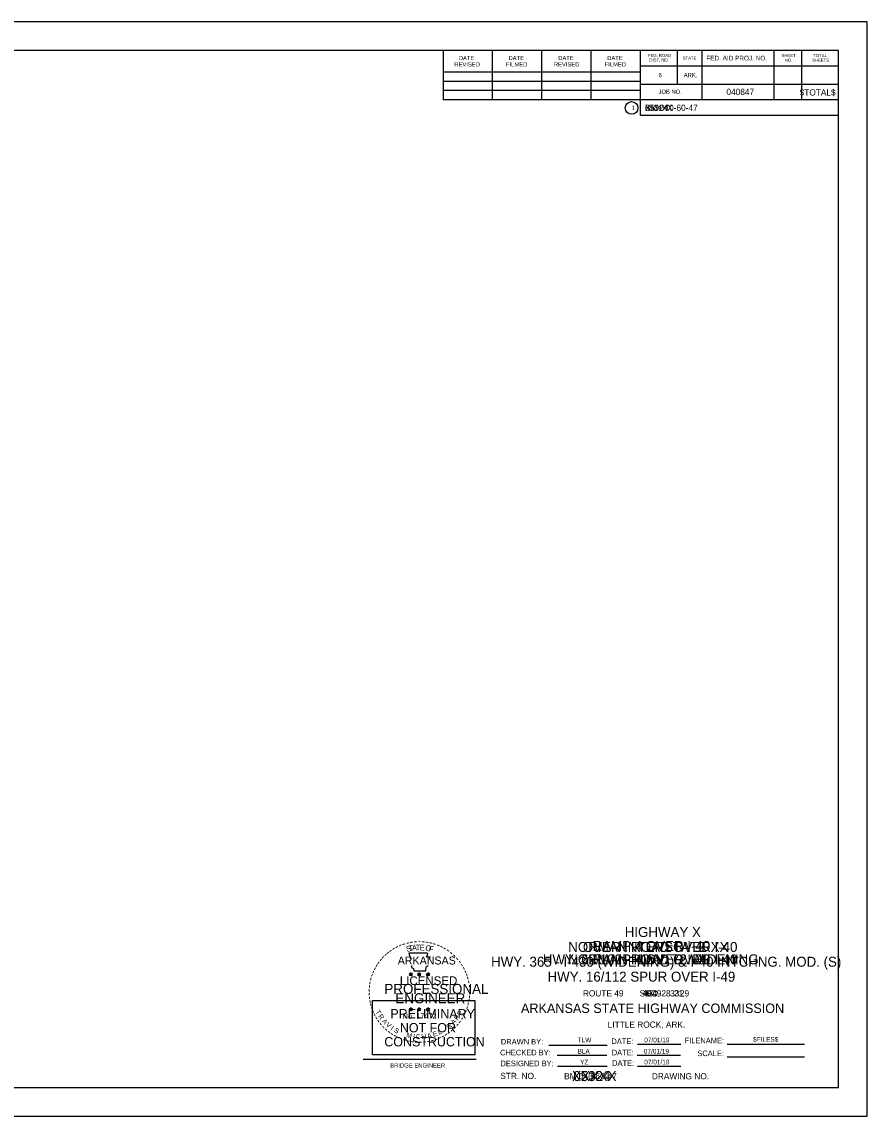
# Model space of a CAD drawing. Extents: x 0 to 2.83, y -2.82 to 1.83.
import ezdxf

# ---------------------------------------------------------------- set-up
doc = ezdxf.new("R2010")
doc.units = 0
for name, color, linetype in [('1', 7, 'Continuous'), ('B-Seal', 7, 'Continuous'), ('B-Tbl-BM0406045', 7, 'Continuous'), ('B-Tbl-BM0406047', 7, 'Continuous'), ('B-Tbl-Bridge A - Details', 7, 'Continuous'), ('B-Tbl-Bridge A - Layout', 7, 'Continuous'), ('B-Tbl-Bridge B - Details', 7, 'Continuous'), ('B-Tbl-Bridge B - Layout', 7, 'Continuous'), ('B-Tbl-Bridge E', 7, 'Continuous'), ('B-Tbl-Bridge F', 7, 'Continuous'), ('B-Tbl-Prelim', 7, 'Continuous'), ('B-Tbl-Title Block', 7, 'Continuous'), ('B-Tbl-Title Block Major Text', 7, 'Continuous'), ('B-Tbl-Title Block Minor Text', 7, 'Continuous'), ('B-Title Block (No Plot)', 7, 'Continuous'), ('Default', 7, 'Continuous'), ('Level 1', 7, 'Continuous'), ('No Plot Border', 7, 'Continuous')]:
    doc.layers.add(name, color=color, linetype=linetype)

# ---------------------------------------------------------------- blocks, each defined once
blk = doc.blocks.new('TMR')
at = {"layer": 'Level 1'}
for p, q in [((-1.08, 2.49), (-0.9, 2.44)), ((-1.08, 2.49), (-0.95, 2.47)), ((-1.08, 2.49), (-0.96, 2.43)), ((-1.01, 2.28), (-0.9, 2.44)), ((-1.01, 2.28), (-0.94, 2.41)), ((-1.01, 2.28), (-0.9, 2.4)), ((-0.9, 2.62), (-0.92, 2.49)), ((-0.9, 2.44), (-0.9, 2.62)), ((-0.9, 2.62), (-0.87, 2.49)), ((-0.72, 2.49), (-0.9, 2.44)), ((-0.79, 2.28), (-0.9, 2.44)), ((-0.79, 2.28), (-0.9, 2.39)), ((-0.72, 2.49), (-0.87, 2.47)), ((-0.79, 2.28), (-0.86, 2.43)), ((-0.72, 2.49), (-0.83, 2.44)), ((-0.23, 2.49), (-0.05, 2.44)), ((-0.23, 2.49), (-0.1, 2.47)), ((-0.23, 2.49), (-0.11, 2.43)), ((-0.16, 2.28), (-0.05, 2.44)), ((-0.16, 2.28), (-0.1, 2.41)), ((-0.16, 2.28), (-0.05, 2.4)), ((-0.05, 2.62), (-0.07, 2.49)), ((-0.05, 2.44), (-0.05, 2.62)), ((-0.05, 2.62), (-0.02, 2.49)), ((0.13, 2.49), (-0.05, 2.44)), ((0.06, 2.28), (-0.05, 2.44)), ((0.06, 2.28), (-0.05, 2.39)), ((0.13, 2.49), (-0.02, 2.47)), ((0.06, 2.28), (-0.01, 2.43)), ((0.13, 2.49), (0.02, 2.44)), ((0.67, 2.49), (0.85, 2.43)), ((0.67, 2.49), (0.8, 2.46)), ((0.67, 2.49), (0.79, 2.42)), ((0.74, 2.28), (0.85, 2.43)), ((0.74, 2.28), (0.8, 2.4)), ((0.74, 2.28), (0.85, 2.39)), ((0.85, 2.62), (0.83, 2.49)), ((0.85, 2.43), (0.85, 2.62)), ((0.85, 2.62), (0.87, 2.49)), ((1.02, 2.49), (0.85, 2.43)), ((0.96, 2.28), (0.85, 2.43)), ((0.96, 2.28), (0.85, 2.39)), ((1.02, 2.49), (0.88, 2.46)), ((0.96, 2.28), (0.89, 2.43)), ((1.02, 2.49), (0.92, 2.43)), ((-1.08, -1.07), (-0.9, -1.13)), ((-1.08, -1.07), (-0.95, -1.09)), ((-1.08, -1.07), (-0.96, -1.13)), ((-0.9, -0.94), (-0.92, -1.07)), ((-0.9, -1.13), (-0.9, -0.94)), ((-0.9, -0.94), (-0.88, -1.07)), ((-0.72, -1.07), (-0.9, -1.13)), ((-0.72, -1.07), (-0.87, -1.1)), ((-0.72, -1.07), (-0.83, -1.12)), ((-0.23, -1.07), (-0.05, -1.13)), ((-0.23, -1.07), (-0.1, -1.09)), ((-0.23, -1.07), (-0.11, -1.13)), ((-0.05, -0.94), (-0.07, -1.07)), ((-0.05, -1.13), (-0.05, -0.94)), ((-0.05, -0.94), (-0.03, -1.07)), ((0.12, -1.07), (-0.05, -1.13)), ((0.12, -1.07), (-0.02, -1.1)), ((0.12, -1.07), (0.02, -1.12)), ((0.67, -1.08), (0.85, -1.13)), ((0.67, -1.08), (0.8, -1.1)), ((0.67, -1.08), (0.79, -1.14)), ((0.85, -0.95), (0.83, -1.07)), ((0.85, -1.13), (0.85, -0.95)), ((0.85, -0.95), (0.87, -1.07)), ((1.02, -1.08), (0.85, -1.13)), ((1.02, -1.08), (0.88, -1.1)), ((1.02, -1.08), (0.92, -1.13)), ((-1.01, -1.28), (-0.9, -1.13)), ((-1.01, -1.28), (-0.95, -1.15)), ((-1.01, -1.28), (-0.9, -1.17)), ((-0.79, -1.28), (-0.9, -1.13)), ((-0.79, -1.28), (-0.9, -1.17)), ((-0.79, -1.28), (-0.86, -1.13)), ((-0.16, -1.28), (-0.05, -1.13)), ((-0.16, -1.28), (-0.1, -1.15)), ((-0.16, -1.28), (-0.05, -1.17)), ((0.06, -1.28), (-0.05, -1.13)), ((0.06, -1.28), (-0.05, -1.17)), ((0.06, -1.28), (-0.01, -1.13)), ((0.74, -1.28), (0.85, -1.13)), ((0.74, -1.28), (0.8, -1.16)), ((0.74, -1.28), (0.85, -1.17)), ((0.96, -1.28), (0.85, -1.13)), ((0.96, -1.28), (0.85, -1.17)), ((0.96, -1.28), (0.89, -1.14))]:
    blk.add_line(p, q, dxfattribs=at)
for points in [[(-1.12, 4.59), (-0.93, 3.99)], [(0.99, 3.99), (1.08, 4.2), (0.71, 4.19), (0.73, 4.29), (0.78, 4.39), (0.82, 4.47), (0.82, 4.54), (0.76, 4.59), (-1.12, 4.59)], [(-0.83, 3.34), (-0.83, 3.13), (-0.62, 3.01), (-0.6, 2.77), (0.61, 2.77), (0.67, 3.19)], [(0.82, 3.34), (0.8, 3.25)], [(-0.9, 2.62), (-0.79, 2.28), (-1.08, 2.49), (-0.72, 2.49), (-1.01, 2.28), (-0.9, 2.62)], [(-0.05, 2.62), (0.06, 2.28), (-0.23, 2.49), (0.13, 2.49), (-0.16, 2.28), (-0.05, 2.62)], [(0.8, 3.25), (0.67, 3.19)], [(0.85, 2.62), (0.96, 2.28), (0.67, 2.49), (1.02, 2.49), (0.74, 2.28), (0.85, 2.62)], [(-0.9, -0.94), (-0.79, -1.28), (-1.08, -1.07), (-0.72, -1.07), (-1.01, -1.28), (-0.9, -0.94)], [(-0.05, -0.94), (0.06, -1.28), (-0.23, -1.07), (0.12, -1.07), (-0.16, -1.28), (-0.05, -0.94)], [(0.85, -0.95), (0.96, -1.28), (0.67, -1.08), (1.02, -1.08), (0.74, -1.28), (0.85, -0.95)]]:
    blk.add_lwpolyline(points, dxfattribs=at)
for centre, radius in [((-0.9, 2.44), 0.0876), ((-0.9, 2.44), 0.0735), ((-0.9, 2.44), 0.0589), ((-0.9, 2.44), 0.0504), ((-0.9, 2.44), 0.038), ((-0.9, 2.44), 0.0252), ((-0.9, 2.44), 0.0151), ((-0.05, 2.44), 0.0876), ((-0.05, 2.44), 0.0735), ((-0.05, 2.44), 0.0589), ((-0.05, 2.44), 0.0504), ((-0.05, 2.44), 0.038), ((-0.05, 2.44), 0.0252), ((-0.05, 2.44), 0.0151), ((0.85, 2.43), 0.0876), ((0.85, 2.43), 0.0735), ((0.85, 2.43), 0.0589), ((0.85, 2.43), 0.0504), ((0.85, 2.43), 0.038), ((0.85, 2.43), 0.0252), ((0.85, 2.43), 0.0151), ((-0.9, -1.13), 0.0876), ((-0.9, -1.13), 0.0735), ((-0.9, -1.13), 0.0589), ((-0.9, -1.13), 0.0504), ((-0.9, -1.13), 0.038), ((-0.9, -1.13), 0.0252), ((-0.9, -1.13), 0.0151), ((-0.05, -1.13), 0.0876), ((-0.05, -1.13), 0.0735), ((-0.05, -1.13), 0.0589), ((-0.05, -1.13), 0.0504), ((-0.05, -1.13), 0.038), ((-0.05, -1.13), 0.0252), ((-0.05, -1.13), 0.0151), ((0.85, -1.13), 0.0876), ((0.85, -1.13), 0.0735), ((0.85, -1.13), 0.0589), ((0.85, -1.13), 0.0504), ((0.85, -1.13), 0.038), ((0.85, -1.13), 0.0252), ((0.85, -1.13), 0.0151)]:
    blk.add_circle(centre, radius, dxfattribs=at)
for s, height, rotation, p in [('-', 0.814, 19.1761, (-1.69, 5.14)), ('-', 0.814, 13.6302, (-1.31, 5.26)), ('-', 0.814, 10.2193, (-0.97, 5.35)), ('-', 0.814, 5.8968, (-0.6, 5.4)), ('-', 0.814, 0.1862, (-0.2, 5.44)), ('-', 0.814, 357.743, (0.17, 5.43)), ('-', 0.814, 352.1617, (0.54, 5.4)), ('-', 0.814, 347.2049, (0.91, 5.35)), ('-', 0.814, 342.3362, (1.23, 5.27)), ('-', 0.814, 42.9622, (-3.4, 4.05)), ('-', 0.814, 38.9507, (-3.18, 4.26)), ('-', 0.814, 36.2317, (-2.93, 4.45)), ('-', 0.814, 34.0636, (-2.64, 4.66)), ('-', 0.814, 28.7918, (-2.34, 4.84)), ('-', 0.814, 24.3072, (-2.02, 5.01)), ('S', 0.583, 14.5321, (-1.3, 4.7)), ('T', 0.583, 11.2896, (-1.07, 4.75)), ('A', 0.583, 5.537, (-0.77, 4.82)), ('T', 0.583, 2.7568, (-0.39, 4.86)), ('E', 0.583, 357.1708, (-0.01, 4.87)), ('O', 0.583, 350.9147, (0.54, 4.84)), ('F', 0.583, 347.7381, (0.88, 4.78)), ('-', 0.814, 337.8551, (1.61, 5.15)), ('-', 0.814, 334.1211, (1.93, 5.02)), ('-', 0.814, 329.6409, (2.22, 4.87)), ('-', 0.814, 325.8627, (2.55, 4.69)), ('-', 0.814, 320.5297, (2.86, 4.47)), ('-', 0.814, 58.0706, (-4.21, 3)), ('-', 0.814, 54.2325, (-4.04, 3.27)), ('-', 0.814, 50.6142, (-3.83, 3.56)), ('-', 0.814, 48.4231, (-3.63, 3.81)), ('-', 0.814, 315.5786, (3.16, 4.22)), ('-', 0.814, 309.8797, (3.45, 3.94)), ('-', 0.814, 306.6522, (3.72, 3.64)), ('-', 0.712, 303.6753, (3.97, 3.35)), ('-', 0.814, 72.3945, (-4.61, 2.06)), ('-', 0.814, 67.7743, (-4.5, 2.38)), ('-', 0.814, 62.8713, (-4.36, 2.69)), ('-', 0.814, 299.6684, (4.13, 3.04)), ('-', 0.814, 294.6628, (4.29, 2.73)), ('-', 0.814, 290.5728, (4.43, 2.44)), ('-', 0.814, 85.1863, (-4.81, 0.98)), ('-', 0.814, 81.2013, (-4.78, 1.33)), ('-', 0.814, 75.461, (-4.71, 1.7)), ('-', 0.814, 285.1233, (4.54, 2.14)), ('-', 0.814, 280.5493, (4.65, 1.76)), ('-', 0.814, 276.5962, (4.73, 1.37)), ('-', 0.814, 89.0622, (-4.83, 0.63)), ('-', 0.814, 94.1959, (-4.81, 0.26)), ('-', 0.814, 98.9479, (-4.77, -0.08)), ('-', 0.814, 263.5172, (4.77, 0.34)), ('-', 0.814, 274.3301, (4.76, 1.01)), ('-', 0.814, 269.9407, (4.78, 0.68)), ('-', 0.814, 101.7149, (-4.7, -0.45)), ('-', 0.814, 105.4578, (-4.62, -0.76)), ('-', 0.814, 109.0874, (-4.51, -1.08)), ('-', 0.814, 252.8681, (4.58, -0.7)), ('-', 0.814, 255.7626, (4.67, -0.33)), ('-', 0.814, 260.9953, (4.73, 0.01)), ('-', 0.814, 114.0643, (-4.38, -1.38)), ('-', 0.814, 115.7289, (-4.23, -1.7)), ('-', 0.814, 120.4471, (-4.05, -1.99)), ('T', 0.5, 298.8548, (-4.53, -1.36)), ('-', 0.814, 125.8934, (-3.84, -2.28)), ('R', 0.5, 305.7927, (-4.26, -1.84)), ('A', 0.5, 312.7306, (-3.87, -2.36)), ('A', 0.5, 46.9035, (3.46, -2.73)), ('P', 0.5, 53.8414, (3.86, -2.3)), ('P', 0.5, 60.7793, (4.21, -1.81)), ('-', 0.814, 239.0712, (4.14, -1.74)), ('-', 0.814, 244.6197, (4.34, -1.36)), ('-', 0.814, 247.8887, (4.47, -1.04)), ('-', 0.814, 130.7181, (-3.61, -2.56)), ('-', 0.814, 134.2238, (-3.34, -2.84)), ('-', 0.814, 138.9338, (-3.08, -3.07)), ('V', 0.5, 319.6685, (-3.49, -2.76)), ('-', 0.814, 144.6463, (-2.79, -3.28)), ('I', 0.5, 324.7123, (-3, -3.17)), ('S', 0.5, 330.5867, (-2.67, -3.4)), ('E', 0.5, 19.5398, (1.42, -3.94)), ('L', 0.5, 26.0898, (1.98, -3.73)), ('R', 0.5, 39.9656, (2.98, -3.16)), ('-', 0.814, 221.0851, (3.2, -2.91)), ('-', 0.814, 225.7653, (3.47, -2.65)), ('-', 0.814, 231.2538, (3.71, -2.36)), ('-', 0.814, 233.8452, (3.93, -2.08)), ('-', 0.814, 148.0898, (-2.51, -3.47)), ('-', 0.814, 151.5704, (-2.21, -3.63)), ('-', 0.814, 154.6002, (-1.95, -3.76)), ('-', 0.814, 158.5612, (-1.63, -3.89)), ('-', 0.814, 162.7983, (-1.28, -4)), ('M', 0.5, 346.9074, (-1.4, -3.96)), ('-', 0.814, 167.5555, (-0.92, -4.08)), ('-', 0.814, 173.1155, (-0.52, -4.14)), ('I', 0.5, 353.155, (-0.7, -4.11)), ('-', 0.814, 176.5183, (-0.14, -4.16)), ('C', 0.5, 358.3383, (-0.41, -4.14)), ('-', 0.814, 181.5918, (0.23, -4.15)), ('H', 0.5, 5.2762, (0.19, -4.15)), ('-', 0.814, 185.8167, (0.65, -4.12)), ('-', 0.814, 191.2858, (1.02, -4.05)), ('A', 0.5, 12.214, (0.82, -4.08)), ('-', 0.814, 195.4743, (1.39, -3.95)), ('-', 0.814, 200.7184, (1.74, -3.82)), ('-', 0.814, 204.2516, (2.05, -3.68)), ('-', 0.814, 207.3568, (2.37, -3.52)), ('-', 0.814, 212.2491, (2.65, -3.35)), ('-', 0.814, 215.7363, (2.92, -3.15))]:
    blk.add_text(s, height=height, rotation=rotation, dxfattribs=at).set_placement(p)
for s, height, p in [('ARKANSAS', 0.81, (-2.23, 3.43)), ('LICENSED', 0.875, (-2.02, 1.35)), ('PROFESSIONAL', 1.0173, (-3.59, 0.44)), ('ENGINEER', 1.017, (-2.47, -0.51)), ('No. 17472', 0.542, (-1.73, -2.09))]:
    blk.add_text(s, height=height, dxfattribs=at).set_placement(p)

msp = doc.modelspace()

# ---------------------------------------------------------------- linework, layer by layer
at = {"layer": '1'}
msp.add_line((1.9889, 0.0952), (2.1782, 0.0952), dxfattribs=at)
at = {"layer": 'B-Tbl-Prelim'}
msp.add_lwpolyline([(2.0042, 0.1937), (2.1758, 0.1937), (2.1758, 0.1025), (2.0042, 0.1025)], close=True, dxfattribs=at)
at = {"layer": 'B-Tbl-Title Block'}
for p, q in [((2.123, 1.7853), (2.123, 1.7027)), ((2.2055, 1.7027), (2.2055, 1.7853)), ((2.288, 1.7027), (2.288, 1.7853)), ((2.3709, 1.7027), (2.3709, 1.7853)), ((2.4534, 1.6769), (2.4534, 1.7853)), ((2.5154, 1.7286), (2.5154, 1.7853)), ((2.5568, 1.7027), (2.5568, 1.7853)), ((2.6769, 1.7853), (2.6769, 1.7027)), ((2.7233, 1.7853), (2.7233, 1.7027)), ((2.4531, 1.7491), (2.123, 1.7491)), ((2.7853, 1.7594), (2.4534, 1.7594)), ((2.4534, 1.7335), (2.123, 1.7335)), ((2.7853, 1.7286), (2.4534, 1.7286)), ((2.4534, 1.7183), (2.123, 1.7183)), ((2.7853, 1.7027), (2.123, 1.7027)), ((2.4534, 1.6769), (2.7853, 1.6769)), ((2.2998, 0.1191), (2.3978, 0.1191)), ((2.4483, 0.1208), (2.5213, 0.1208)), ((2.599, 0.1208), (2.7284, 0.1208)), ((2.3136, 0.102), (2.397, 0.102)), ((2.4477, 0.102), (2.5206, 0.102)), ((2.599, 0.0994), (2.7284, 0.0994)), ((2.3142, 0.0837), (2.3975, 0.0837)), ((2.4483, 0.0837), (2.5213, 0.0837))]:
    msp.add_line(p, q, dxfattribs=at)
msp.add_lwpolyline([(2.7853, 1.7853), (0.1263, 1.7853), (0.1263, 0.0481), (2.7853, 0.0481)], close=True, dxfattribs=at)
msp.add_circle((2.4385, 1.6891), 0.0106, dxfattribs=at)
at = {"layer": 'B-Title Block (No Plot)'}
msp.add_line((2.8035, 1.8045), (2.8035, 1.8045), dxfattribs=at)
at = {"layer": 'No Plot Border'}
msp.add_lwpolyline([(0, 0), (2.8333, 0), (2.8333, 1.8333), (0, 1.8333)], close=True, dxfattribs=at)

# ---------------------------------------------------------------- block references
at = {"layer": 'B-Seal', "xscale": 0.016480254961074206, "yscale": 0.016480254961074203}
msp.add_blockref('TMR', (2.0834, 0.1975), dxfattribs=at)

# ---------------------------------------------------------------- texts
at = {"layer": '1'}
msp.add_text('BRIDGE ENGINEER', height=0.007147, dxfattribs=at).set_placement((2.0339, 0.0814))
at = {"layer": 'B-Tbl-BM0406045'}
for s, height, p in [('HWY. 62/102 - HWY. 72 WIDENING', 0.016667, (2.2898, 0.2543)), ('I-49        29', 0.010417, (2.4646, 0.2004))]:
    msp.add_text(s, height=height, rotation=0, dxfattribs=at).set_placement(p)
at = {"layer": 'B-Tbl-BM0406047'}
for s, height, p in [('BM 040-60-47', 0.010417, (2.4611, 1.6842)), ('RAMP 4 OVER I-40', 0.016667, (2.3734, 0.2543)), ('40        33', 0.010417, (2.4566, 0.2005)), ('BM 040-60-47', 0.010417, (2.3255, 0.0617))]:
    msp.add_text(s, height=height, rotation=0, dxfattribs=at).set_placement(p)
at = {"layer": 'B-Tbl-Bridge A - Details'}
for s, height, p in [('05324', 0.01042, (2.4611, 1.6842)), ('RAMP 4 OVER I-40', 0.016667, (2.3734, 0.2543)), ('430       21', 0.010417, (2.459, 0.2005)), ('05324', 0.01667, (2.3409, 0.0587))]:
    msp.add_text(s, height=height, rotation=0, dxfattribs=at).set_placement(p)
at = {"layer": 'B-Tbl-Bridge A - Layout'}
for s, height, p in [('05324', 0.01042, (2.4611, 1.6842)), ('RAMP 4 OVER I-40', 0.016667, (2.3734, 0.2767)), ('HWY. 365 - I-430 (WIDENING) & I-40 INTCHNG. MOD. (S)', 0.016667, (2.2031, 0.2503)), ('430       21', 0.010417, (2.459, 0.2005)), ('05324', 0.01667, (2.3409, 0.0587))]:
    msp.add_text(s, height=height, rotation=0, dxfattribs=at).set_placement(p)
at = {"layer": 'B-Tbl-Bridge B - Details'}
for s, height, p in [('XXXXX', 0.01042, (2.4611, 1.6842)), ('NORMAN ROAD OVER I-40', 0.016667, (2.3324, 0.2543)), ('40        33', 0.010417, (2.4566, 0.2005)), ('XXXXX', 0.01667, (2.3389, 0.0587))]:
    msp.add_text(s, height=height, rotation=0, dxfattribs=at).set_placement(p)
at = {"layer": 'B-Tbl-Bridge B - Layout'}
for s, height, p in [('XXXXX', 0.01042, (2.4611, 1.6842)), ('NORMAN ROAD OVER I-40', 0.016667, (2.3324, 0.2751)), ('HWY. 365 - I-430 (WIDENING) & I-40 INTCHNG. MOD. (S)', 0.016667, (2.2031, 0.2503)), ('40        33', 0.010417, (2.4566, 0.2005)), ('XXXXX', 0.01667, (2.3389, 0.0587))]:
    msp.add_text(s, height=height, rotation=0, dxfattribs=at).set_placement(p)
at = {"layer": 'B-Tbl-Bridge E'}
for s, height, p in [('XXXXX', 0.01042, (2.4611, 1.6842)), ('HIGHWAY X', 0.01667, (2.4271, 0.3001)), ('OVER INTERSTATE XX', 0.016667, (2.3569, 0.2751)), ('XXXXX', 0.01667, (2.3389, 0.0587))]:
    msp.add_text(s, height=height, rotation=0, dxfattribs=at).set_placement(p)
at = {"layer": 'B-Tbl-Bridge F'}
for s, height, p in [('XXXXX', 0.01042, (2.4611, 1.6842)), ('HIGHWAY X', 0.01667, (2.4271, 0.3001)), ('OVER INTERSTATE XX', 0.016667, (2.3569, 0.2751)), ('XXXXX', 0.01667, (2.3389, 0.0587))]:
    msp.add_text(s, height=height, rotation=0, dxfattribs=at).set_placement(p)
at = {"layer": 'B-Tbl-Prelim'}
for s, height, p in [('PRELIMINARY', 0.015625, (2.0343, 0.1637)), ('NOT FOR', 0.01562, (2.0502, 0.1403)), ('CONSTRUCTION', 0.015625, (2.0241, 0.1168))]:
    msp.add_text(s, height=height, dxfattribs=at).set_placement(p)
at = {"layer": 'B-Tbl-Title Block'}
for s, height, p in [('1', 0.00708, (2.4385, 1.6861)), ('DRAWN BY:', 0.00937, (2.2195, 0.12)), ('DATE:', 0.00937, (2.4048, 0.1207)), ('FILENAME:', 0.00937, (2.5274, 0.1219)), ('CHECKED BY:', 0.009375, (2.2181, 0.1018)), ('DATE:', 0.00937, (2.4054, 0.1018)), ('DESIGNED BY:', 0.009375, (2.2188, 0.0836)), ('DATE:', 0.00937, (2.406, 0.0842)), ('SCALE:', 0.00937, (2.5488, 0.1005))]:
    msp.add_text(s, height=height, rotation=0, dxfattribs=at).set_placement(p)
at = {"layer": 'B-Tbl-Title Block Major Text'}
for s, height, p in [('HWY. 16/112 SPUR OVER I-49', 0.016667, (2.2977, 0.2253)), ('ROUTE 49       SEC. 28   ', 0.010417, (2.3569, 0.2005)), ('ARKANSAS STATE HIGHWAY COMMISSION', 0.015833, (2.2532, 0.1728)), ('LITTLE ROCK, ARK.', 0.010417, (2.3985, 0.1481))]:
    msp.add_text(s, height=height, rotation=0, dxfattribs=at).set_placement(p)
at = {"layer": 'B-Tbl-Title Block Minor Text'}
for s, height, p in [('FED. ROAD', 0.00517, (2.4659, 1.7746)), ('SHEET', 0.00517, (2.6897, 1.7744)), ('TOTAL', 0.00517, (2.743, 1.7743)), ('REVISED', 0.00708, (2.1415, 1.7586)), ('DATE', 0.00708, (2.1489, 1.7693)), ('FILMED', 0.00708, (2.228, 1.7586)), ('DATE', 0.00708, (2.2323, 1.7693)), ('REVISED', 0.00708, (2.3082, 1.7586)), ('DATE', 0.00708, (2.3156, 1.7693)), ('FILMED', 0.00708, (2.3934, 1.7586)), ('DATE', 0.00708, (2.3977, 1.7693)), ('DIST. NO.', 0.00517, (2.4684, 1.7669)), ('STATE', 0.00517, (2.5242, 1.77)), ('FED. AID PROJ. NO.', 0.00775, (2.5639, 1.7688)), ('NO.', 0.00517, (2.6954, 1.7666)), ('SHEETS', 0.00517, (2.741, 1.7666)), ('6', 0.00708, (2.4838, 1.7407)), ('ARK.', 0.00708, (2.526, 1.7407)), ('JOB NO.', 0.00708, (2.4837, 1.7128)), ('040847', 0.01042, (2.5975, 1.7109))]:
    msp.add_text(s, height=height, rotation=0, dxfattribs=at).set_placement(p)
for s, height, p in [('$TOTAL$', 0.01042, (2.7202, 1.7099)), ('TLW', 0.00786, (2.3482, 0.1237)), ('07/01/19', 0.00786, (2.4598, 0.1237)), ('$FILES$', 0.00786, (2.6422, 0.1247)), ('BLA', 0.00786, (2.348, 0.1048)), ('07/01/19', 0.00786, (2.4591, 0.1048)), ('YZ', 0.00786, (2.3523, 0.0866)), ('07/01/19', 0.00786, (2.4598, 0.0866))]:
    msp.add_text(s, height=height, dxfattribs=at).set_placement(p)
at = {"layer": 'Default'}
for s, height, p in [('STR. NO.', 0.01042, (2.2185, 0.0621)), ('DRAWING NO.', 0.010417, (2.4725, 0.0616))]:
    msp.add_text(s, height=height, rotation=0, dxfattribs=at).set_placement(p)

doc.saveas('drawing.dxf')
